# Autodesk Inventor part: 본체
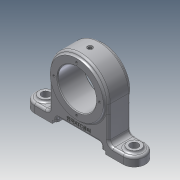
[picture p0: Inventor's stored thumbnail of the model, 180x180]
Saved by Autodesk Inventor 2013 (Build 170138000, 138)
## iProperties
Created: 2019-05
Part Number: 본체
Material: 알루미늄 6061
Document SubType Name: Modeling
Designer: 00
Density: 2.71 g/cm^3
Mass: 457.703 g
Surface Area: 318.8 cm^2
Volume: 168.894 cm^3
Author: 00
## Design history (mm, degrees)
sketch "스케치1"
  geometry: L1 (-40, -60)-(40, -60); L2 (40, -60)-(40, 0); L3 (40, 0)-(-40, 0); L4 (-40, 0)-(-40, -60); C1 r 40 at (0, 0); 1 further point
  constraints: 8 end point, 2 midpoint, 2 parallel, 1 centre point, 1 coincident, 1 horizontal, 1 perpendicular
  dimensions: "d0" = 80 distance of L3.end L2.end; "d1" = 60 distance of L2.end L1.end; "d3" = 80 diameter of C1
extrude "돌출1" new body sketch "스케치1" stored distance "d4" = 30; taper "d5" = 0 deg
sketch "스케치2"
  geometry: C1 r 36 at (0, 0); 1 further point
  constraints: 1 centre point, 1 coincident
  dimensions: "d6" = 72 diameter of C1
extrude "돌출2" join sketch "스케치2" stored distance "d7" = 36; taper "d8" = 0 deg
sketch "스케치3"
  geometry: C1 r 36 at (0, 0) reference; C2 r 26 at (0, 0)
  constraints: 1 centre point, 1 coincident
  dimensions: "d9" = 52 diameter of C2
extrude "돌출3" cut sketch "스케치3" stored distance "d10" = 36; taper "d11" = 0 deg
sketch "스케치4"
  geometry: L1 (0, 0)-(0, 31); C1 r 36 at (0, 0) reference; 1 further point
  constraints: 2 end point, 1 coincident, 1 vertical
  dimensions: "d12" = 31 distance of L1.start L1.end
hole "구멍1" sketch "스케치4" at (0, 31) diameter "d13" = 3.242; stored, may be unused: countersink angle "d17" = 90 deg, drill point angle "d19" = 118 deg; dims "d14" = 6, "d15" = 4, "d16" = 2, "d18" = 8
node "작업 평면1"
sketch "스케치5"
  geometry: 2 further points
  constraints: 1 coincident
hole "구멍2" sketch "스케치5" at (0, 0) diameter "d24" = 4.917; stored, may be unused: countersink angle "d28" = 90 deg, drill point angle "d30" = 118 deg; dims "d25" = 8, "d26" = 7, "d27" = 1, "d29" = 10
sketch "스케치6"
  geometry: L1 (80, -30)-(80, 0) reference; L2 (0, 0)-(80, 0) reference; L3 (0, 0)-(0, -30) reference; L4 (80, -30)-(0, -30) reference; L5 (100, -30)-(-20, -30); L6 (-20, -30)-(-20, 0); L7 (-20, 0)-(100, 0); L8 (100, 0)-(100, -30); L9 (100, -30)-(-20, 0); L10 (-20, -30)-(100, 0); C1 r 15 at (-20, -15); C2 r 15 at (100, -15); 1 further point
  constraints: 12 end point, 4 midpoint, 2 centre point, 2 parallel, 1 horizontal, 1 perpendicular
  dimensions: "d31" = 120 distance of L6.end L7.end; "d32" = 30 distance of L5.end L6.end; "d33" = 30 diameter of C1; "d34" = 30 diameter of C2
extrude "돌출4" join sketch "스케치6" distance "d35" = 12; taper "d36" = 0 deg
sketch "스케치7"
  geometry: C1 r 9 at (-20, 15); A1 r 15 centre (-20, 15) between (-20, 30) and (-20, 0) reference; 1 further point
  constraints: 1 centre point, 1 coincident
  dimensions: "d37" = 18 diameter of C1
extrude "돌출5" join sketch "스케치7" distance "d38" = 3; taper "d39" = 0 deg
sketch "스케치8"
  geometry: C1 r 9 at (0, 0) reference; 2 further points
  constraints: 1 coincident
hole "구멍3" sketch "스케치8" at (0, 0) diameter "d40" = 11; stored, may be unused: countersink angle "d44" = 90 deg, drill point angle "d46" = 118 deg; dims "d41" = 8, "d42" = 7, "d43" = 1, "d45" = 10
sketch "스케치9"
  geometry: L1 (-60, -60)-(60, -60) reference; L2 (-36, -60)-(36, -60); L3 (36, -60)-(36, -56); L4 (36, -56)-(-36, -56); L5 (-36, -56)-(-36, -60); 1 further point
  constraints: 8 end point, 2 midpoint, 2 parallel, 1 horizontal, 1 perpendicular
  dimensions: "d47" = 72 distance of L4.end L3.end; "d48" = 4 distance of L3.end L2.end
extrude "돌출6" cut sketch "스케치9" stored distance "d49" = 3; taper "d50" = 0 deg
sketch "스케치10"
  geometry: L1 (-36, -56)-(36, -56) reference; L2 (-30, -56)-(30, -56); L3 (30, -56)-(30, -50); L4 (30, -50)-(-30, -50); L5 (-30, -50)-(-30, -56); 1 further point
  constraints: 8 end point, 2 midpoint, 2 parallel, 1 horizontal, 1 perpendicular
  dimensions: "d51" = 60 distance of L4.end L3.end; "d52" = 6 distance of L3.end L2.end
extrude "돌출7" cut sketch "스케치10" stored distance "d53" = 3; taper "d54" = 0 deg
node "작업 평면2"
sketch "스케치11"
  geometry: 2 further points
  constraints: 1 coincident
hole "구멍4" sketch "스케치11" at (0, 0) diameter "d56" = 2; stored, may be unused: countersink angle "d60" = 90 deg, drill point angle "d62" = 118 deg; dims "d57" = 8, "d58" = 7, "d59" = 1, "d61" = 10
sketch "스케치12"
  geometry: C1 r 1.5 at (0, 26); 1 further point
  constraints: 2 vertical alignment, 1 centre point, 1 other
  dimensions: "d63" = 3 diameter of C1
extrude "돌출8" cut sketch "스케치12" stored distance "d64" = 3; taper "d65" = 0 deg
chamfer "모따기1" distance "d66" = 1; stored, may be unused: second distance "d67" = 2, angle "d68" = 45 deg
fillet "모깎기1" dims "d69" = 6
sketch "스케치13"
  geometry: L1 (-30, -50)-(30, -50) reference; A1 r 40 centre (0, 0) between (40, 0) and (-40, 0) reference; 1 further point
  constraints: 1 vertical alignment, 1 other
  dimensions: "d70" = 7 distance from line of point (0, -43) L1
feature "엠보싱1" sketch "스케치13" dims "d0" = 80, "d1" = 60, "d71" = 0.5, "d72" = 0
fillet "모깎기2" dims "d73" = 3
fillet "모깎기3" dims "d74" = 3
fillet "모깎기4" dims "d75" = 3
fillet "모깎기5" dims "d76" = 3
node "솔리드1"
pattern_circular "원형 패턴1" dims angle "d21" = 360 deg
mirror "대칭1"
mirror "대칭2"
other parameters: "d55" = 26
